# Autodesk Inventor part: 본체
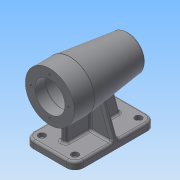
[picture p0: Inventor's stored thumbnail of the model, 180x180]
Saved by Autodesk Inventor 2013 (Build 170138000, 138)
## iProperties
Created: 2018-09
Part Number: 본체
Material: 일반
Document SubType Name: Modeling
Designer: Administrator
Density: 1 g/cm^3
Author: Administrator
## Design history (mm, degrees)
sketch "스케치1"
  geometry: L1 (-56, 0)-(56, 0); L2 (-56, 0)-(-56, 34); L3 (-56, 34)-(-28, 34); L4 (-28, 34)-(52.27, 24.144); A1 r 80 centre (-24, 0) between (56, 0) and (52.27, 24.144); 2 further points
  constraints: 8 end point, 2 coincident, 2 perpendicular, 2 point on circle, 1 centre point, 1 horizontal, 1 midpoint, 1 point on line
  dimensions: "d0" = 112 distance of L1.start L1.end; "d2" = 68 diameter of L3 L1; "d3" = 80 radius of A1; "d4" = 7 deg angle of L4 L3; "d5" = 28 distance of L2.end L3.end
revolve "회전1" sketch "스케치1" stored, may be unused: angle "d6" = 90 deg
node "작업 평면1"
sketch "스케치2"
  geometry: L1 (-23, -56)-(23, -56); L2 (35, -44)-(35, 44); L3 (23, 56)-(-23, 56); L4 (-35, 44)-(-35, -44); A1 r 12 centre (-23, -44) between (-35, -44) and (-23, -56); A2 r 12 centre (23, -44) between (23, -56) and (35, -44); A3 r 12 centre (23, 44) between (35, 44) and (23, 56); A4 r 12 centre (-23, 44) between (-23, 56) and (-35, 44); 6 further points
  constraints: 8 end point, 8 point on circle, 8 tangent, 6 point on line, 4 centre point, 3 equal radius, 2 midpoint, 2 parallel, 1 horizontal, 1 horizontal alignment, 1 perpendicular, 1 vertical alignment
  dimensions: "d8" = 112 distance of point (-35, 56) point (-35, -56); "d10" = 70 distance of point (-35, -56) point (35, -56); "d11" = 12 radius of A1
extrude "돌출1" join sketch "스케치2" distance "d12" = 10; taper "d13" = 0 deg
sketch "스케치3"
  geometry: L1 (-35, -74)-(-35, -64) reference; L2 (-35, -64)-(35, -64) reference; L3 (35, -64)-(35, -74) reference; L4 (35, -74)-(-35, -74) reference; L5 (0, -20)-(0, -64); L6 (35, -64)-(16.049, -11.934); L7 (35, -64)-(0, -64); C1 r 30.562 at (0, 0) reference; A1 r 20 centre (0, 0) between (0, -20) and (16.049, -11.934); 1 further point
  constraints: 6 end point, 2 point on circle, 1 centre point, 1 coincident, 1 collinear, 1 midpoint
  dimensions: "d14" = 20 deg angle of L6 L3; "d15" = 90 deg angle of L5 L2
extrude "돌출2" join sketch "스케치3" stored distance "d16" = 8; taper "d17" = 0 deg
node "작업 평면2"
sketch "스케치4"
  geometry: L1 (56, 34)-(56, -34) reference; L2 (28, 34)-(56, 34) reference; L3 (-52.27, 24.144)-(28, 34) reference; L4 (-4, -30.071)-(-52.27, -24.144) reference; L5 (-4, -64)-(-4, -30.071) reference; L6 (-56, -64)-(-4, -64) reference; L7 (-56, -74)-(-56, -64) reference; L8 (56, -74)-(-56, -74) reference; L9 (56, -64)-(56, -74) reference; L10 (4, -64)-(56, -64) reference; L11 (4, -31.053)-(4, -64) reference; L12 (28, -34)-(4, -31.053) reference; L13 (56, -34)-(28, -34) reference; L14 (-25.942, -19)-(-38, -64); L15 (-38, -64)-(38, -64); L16 (38, -64)-(38, -19); L17 (-20, -19)-(38, -19); L18 (-20, -19)-(-25.942, -19); A1 r 80 centre (24, 0) between (-52.27, 24.144) and (-52.27, -24.144) reference; 1 further point
  constraints: 10 end point, 2 parallel, 2 point on line, 1 collinear, 1 perpendicular
  dimensions: "d19" = 105 deg angle of L14 L6; "d20" = 18 distance of L14.end L6.start; "d21" = 18 distance of L9.start L15.end; "d91" = 45 distance between parallel lines of L17 L15
extrude "돌출3" join sketch "스케치4" stored distance "d22" = 8; taper "d23" = 0 deg
node "작업 평면3"
sketch "스케치5"
  geometry: L1 (-56, 34)-(-28, 34) reference; L2 (-28, 34)-(52.27, 24.144) reference; L3 (52.27, -24.144)-(28.115, -27.11) reference; L4 (28.115, -27.11)-(38, -64) reference; L5 (38, -64)-(56, -64) reference; L6 (56, -64)-(56, -74) reference; L7 (56, -74)-(-56, -74) reference; L8 (-56, -74)-(-56, -64) reference; L9 (-56, -64)-(-38, -64) reference; L10 (-38, -64)-(-38, -34) reference; L11 (-38, -34)-(-56, -34) reference; L12 (-56, -34)-(-56, 34) reference; L13 (-56, 0)-(56, 0); L14 (-56, 0)-(-56, 21); L15 (-56, 21)-(-41, 21); L16 (-41, 21)-(-41, 21); L17 (-38, 24)-(10, 24); L18 (13, 21)-(13, 21); L19 (13, 21)-(24.7, 21); L20 (25, 20.7)-(25, 17.5); L21 (25, 17.5)-(42.7, 17.5); L22 (43, 17.2)-(43, 16); L23 (43, 16)-(46.7, 16); L24 (47, 15.7)-(47, 10.5); L25 (47, 10.5)-(47, 10.5); L26 (50, 7.5)-(50, 0); A1 r 80 centre (-24, 0) between (52.27, -24.144) and (52.27, 24.144) reference; A2 r 0.3 centre (24.7, 20.7) between (25, 20.7) and (24.7, 21); A3 r 0.3 centre (42.7, 17.2) between (43, 17.2) and (42.7, 17.5); A4 r 0.3 centre (46.7, 15.7) between (47, 15.7) and (46.7, 16); A5 r 3 centre (-38, 21) between (-38, 24) and (-41, 21); A6 r 3 centre (10, 21) between (13, 21) and (10, 24); A7 r 3 centre (47, 7.5) between (50, 7.5) and (47, 10.5); 7 further points
  constraints: 28 end point, 14 point on line, 13 point on circle, 12 tangent, 6 centre point, 6 parallel, 5 perpendicular, 3 equal radius, 1 collinear, 1 midpoint
  dimensions: "d25" = 42 diameter of L15 L13; "d27" = 15 distance of L14.end L15.end; "d28" = 48 diameter of L17 L13; "d29" = 54 distance of point (-41, 24) point (13, 24); "d30" = 42 diameter of L19 L13; "d31" = 12 distance of L18.end point (25, 21); "d32" = 18 distance of L20.end point (43, 17.5); "d33" = 35 diameter of L21 L13; "d34" = 4 distance of L22.end point (47, 16); "d35" = 32 diameter of L23 L13; "d36" = 3 distance of L24.end point (50, 10.5); "d37" = 21 diameter of L25 L13; "d38" = 0.3 radius of A2; "d39" = 3 radius of A5; "d40" = 3 radius of A7
revolve "회전2" sketch "스케치5" stored, may be unused: angle "d41" = 90 deg
sketch "스케치6"
  geometry: A1 r 12 centre (-23, -44) between (-35, -44) and (-23, -56) reference; A2 r 12 centre (23, -44) between (23, -56) and (35, -44) reference; 1 further point
hole "구멍1" sketch "스케치6" at (-23, -44), (23, -44) diameter "d42" = 5.5; stored, may be unused: countersink angle "d46" = 90 deg, drill point angle "d48" = 118 deg; dims "d43" = 6, "d44" = 9.5, "d45" = 5.4, "d47" = 8
sketch "스케치7"
  geometry: L1 (0, 88)-(0, 0) reference; L2 (0, -12)-(10, -12) reference; 2 further points
  constraints: 1 other
  dimensions: "d49" = 3 distance from line of point (3, 44) L1; "d50" = 56 distance from line of point (3, 44) L2
extrude "돌출4" join sketch "스케치7" distance "d51" = 0.5; taper "d52" = 0 deg
sketch "스케치8" dims "d53" = 52
  geometry: C1 r 21 at (0, 0) reference; C2 r 34 at (0, 0) reference; 2 further points
  constraints: 2 vertical alignment, 1 coincident, 2 other
hole "구멍2" sketch "스케치8" at (0, 26) diameter "d55" = 3.242; stored, may be unused: countersink angle "d59" = 90 deg, drill point angle "d61" = 118 deg; dims "d56" = 8, "d57" = 9.5, "d58" = 5.4, "d60" = 11
fillet "모깎기1" dims "d65" = 3
fillet "모깎기5" dims "d69" = 3
fillet "모깎기32" dims "d97" = 3
fillet "모깎기34" dims "d99" = 3
fillet "모깎기35" dims "d100" = 3
fillet "모깎기37" dims "d102" = 3
fillet "모깎기38" dims "d103" = 3
fillet "모깎기39" dims "d104" = 3
fillet "모깎기40" dims "d105" = 3
node "솔리드1"
mirror "대칭1"
mirror "대칭2"
pattern_circular "원형 패턴1" dims angle "d63" = 360 deg
node "절단 모서리 투영1"
node "절단 모서리 투영2"
node "절단 모서리 투영3"
other parameters: "d7" = -74, "d18" = 0, "d24" = 0
